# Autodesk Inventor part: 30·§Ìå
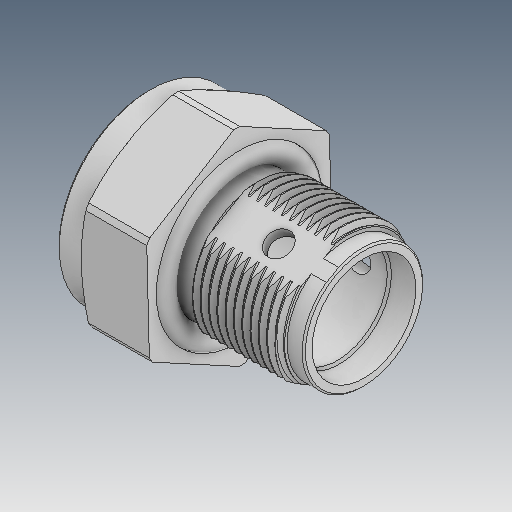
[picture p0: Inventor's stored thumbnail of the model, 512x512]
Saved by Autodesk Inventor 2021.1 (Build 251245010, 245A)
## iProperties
Created: 2019-12
Part Number: 30·§Ìå
Material: Ogólny
Document SubType Name: Modeling
Designer: user
Density: 1 g/cm^3
Appearance: Domyślna
Author: user
Revision Number: ÈÎºÎ
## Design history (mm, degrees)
feature "ÊäÈë1"
feature "ÊäÈë2"
node "Bryła1"
node "Bryła2"
